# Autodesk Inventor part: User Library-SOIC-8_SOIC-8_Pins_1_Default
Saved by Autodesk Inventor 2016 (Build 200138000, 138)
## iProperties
Created: 2012-01
Part Number: User Library-SOIC-8_SOIC-8_Pins_1_Default
Document SubType Name: Modeling
Designer: Trevor
Density: 1 g/cm^3
Material: Generic
Appearance: 200,200,220
Author: Trevor
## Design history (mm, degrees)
feature "Base1"
node "Imported1"
